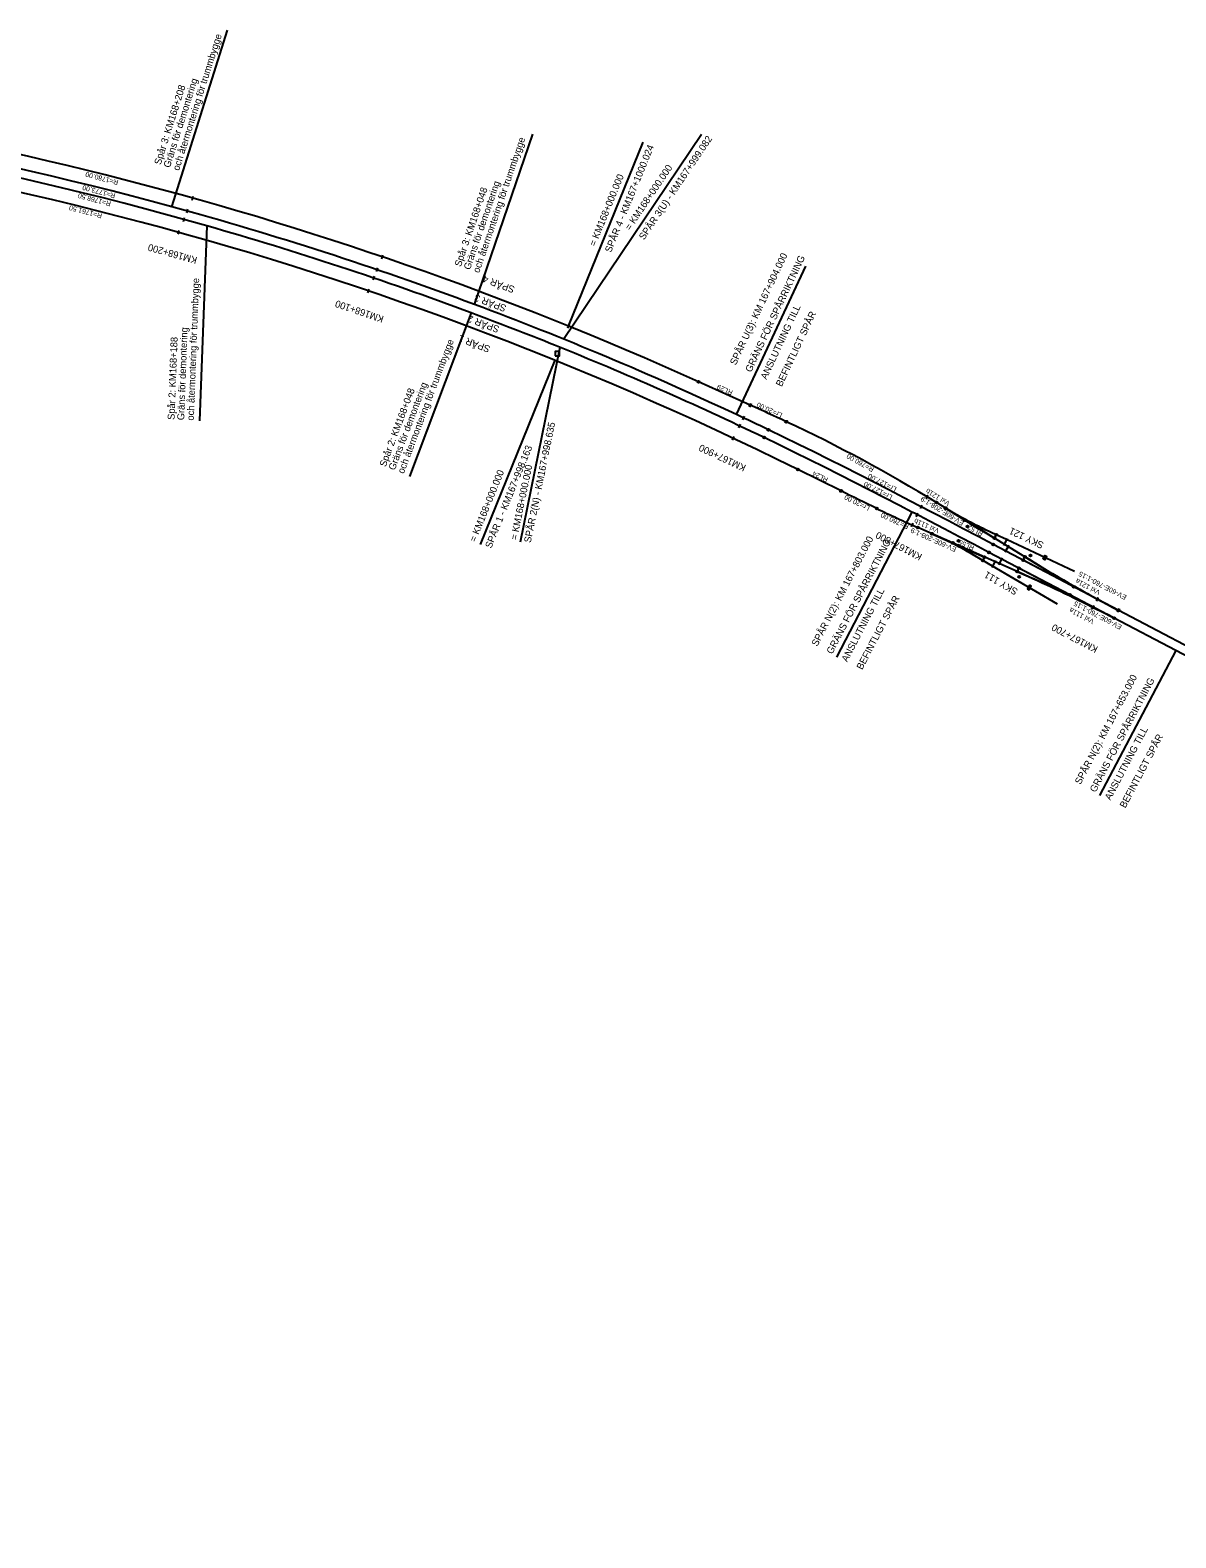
# Model space of a CAD drawing. Extents: x 185262 to 188870, y 6548921 to 6550022.
# Drawn here: x 186997 to 187573, y 6549174 to 6549933 of the extents above; entities that cross this region are included whole.
import ezdxf

# ---------------------------------------------------------------- set-up
doc = ezdxf.new("R2010")
doc.units = 0
for name, color, linetype in [('Befintligt spår som justeras', 7, 'Continuous'), ('BKS 1 verklig mangan P', 7, 'Continuous'), ('BKS 2 verklig mangan P', 7, 'Continuous'), ('FSK P', 7, 'Continuous'), ('Gräns för anslutning L', 7, 'Continuous'), ('Gräns för anslutning T', 7, 'Continuous'), ('Gräns för trummor L', 7, 'Continuous'), ('Gräns för trummor T', 7, 'Continuous'), ('Hinderpåle P', 7, 'Continuous'), ('Kilometertavla P', 7, 'Continuous'), ('Konnektion längdmätning L', 7, 'Continuous'), ('Konnektion längdmätning T', 7, 'Continuous'), ('Längdm markering (primär) L', 7, 'Continuous'), ('Längdmätning T', 7, 'Continuous'), ('MKP fiktiv P', 7, 'Continuous'), ('Spår bef projekterat behålls L', 7, 'Continuous'), ('Spår nr T', 7, 'Continuous'), ('Spår som demonteras och återmonteras', 7, 'Continuous'), ('Spårgeometri T', 7, 'Continuous'), ('Spårmitt projekterad L', 7, 'Continuous'), ('Spårmitt tp P', 7, 'Continuous'), ('Stoppbock P', 7, 'Continuous'), ('Växel linjevikt 2 L', 7, 'Continuous'), ('Växelnummer T', 7, 'Continuous'), ('Växeltyp T', 7, 'Continuous')]:
    doc.layers.add(name, color=color, linetype=linetype)

msp = doc.modelspace()

# ---------------------------------------------------------------- linework, layer by layer
at = {"layer": 'Befintligt spår som justeras'}
for p, q in [((187719.61, 6549548.75), (187481.29, 6549674.04)), ((187573.24, 6549620.62), (187479.19, 6549670.06))]:
    msp.add_line(p, q, dxfattribs=at)
for points in [[(187481.29, 6549674.04), (187473.8, 6549677.98), (187466.3, 6549681.92), (187458.8, 6549685.85), (187451.3, 6549689.78), (187443.8, 6549693.69), (187436.28, 6549697.59), (187428.76, 6549701.48), (187421.23, 6549705.36), (187413.69, 6549709.21), (187406.14, 6549713.04), (187398.58, 6549716.85), (187391.01, 6549720.63), (187383.42, 6549724.38), (187375.81, 6549728.1), (187368.19, 6549731.79)], [(187479.19, 6549670.06), (187471.7, 6549674), (187464.2, 6549677.94), (187456.7, 6549681.87), (187449.2, 6549685.8), (187441.7, 6549689.71), (187440.46, 6549690.35)]]:
    msp.add_lwpolyline(points, dxfattribs=at)
msp.add_arc((186599.87, 6548133.91), 1773, 64.32006, 64.89363, dxfattribs=at)
at = {"layer": 'BKS 1 verklig mangan P'}
for centre in [(187481.99, 6549677.2), (187476.99, 6549667.69), (187496.38, 6549666.11), (187494.28, 6549662.13)]:
    msp.add_circle(centre, 0.5, dxfattribs=at)
at = {"layer": 'BKS 2 verklig mangan P'}
for centre in [(187482.91, 6549678.9), (187476.11, 6549665.97), (187497.33, 6549667.78), (187493.45, 6549660.39)]:
    msp.add_circle(centre, 0.5, dxfattribs=at)
at = {"layer": 'FSK P'}
for centre in [(187457.26, 6549692.38), (187450.46, 6549679.46), (187542.27, 6549636.9), (187544.37, 6549640.88)]:
    msp.add_circle(centre, 0.5, dxfattribs=at)
at = {"layer": 'Gräns för anslutning L'}
for p, q in [((187352.15, 6549739.4), (187387.13, 6549814.04)), ((187440.46, 6549690.35), (187402.42, 6549617.23)), ((187573.24, 6549620.62), (187534.89, 6549547.66))]:
    msp.add_line(p, q, dxfattribs=at)
at = {"layer": 'Gräns för trummor L'}
for p, q in [((187068.08, 6549843.97), (187096.09, 6549932.91)), ((187220.28, 6549794.82), (187249.63, 6549880.48)), ((187085.63, 6549834.39), (187081.91, 6549736.23)), ((187218.59, 6549790.65), (187187.52, 6549708.32))]:
    msp.add_line(p, q, dxfattribs=at)
at = {"layer": 'Hinderpåle P'}
for centre, radius in [((187468.41, 6549683.13), 0.5), ((187468.41, 6549683.13), 0.2), ((187463.81, 6549675.8), 0.5), ((187463.81, 6549675.8), 0.2), ((187500.14, 6549668.49), 0.5), ((187500.14, 6549668.49), 0.2), ((187494.46, 6549657.68), 0.5), ((187494.46, 6549657.68), 0.2)]:
    msp.add_circle(centre, radius, dxfattribs=at)
at = {"layer": 'Kilometertavla P'}
msp.add_lwpolyline([(187260.9, 6549768.91), (187263.15, 6549768.91), (187263.15, 6549771.16), (187260.9, 6549771.16)], close=True, dxfattribs=at)
at = {"layer": 'Konnektion längdmätning L'}
for points in [[(187265.02, 6549777.42), (187334.47, 6549880.58)], [(187267.64, 6549783.91), (187305.16, 6549876.6)], [(187263.33, 6549773.25), (187243.33, 6549675.26)], [(187260.7, 6549766.76), (187223.18, 6549674.06)]]:
    msp.add_lwpolyline(points, dxfattribs=at)
at = {"layer": 'Längdm markering (primär) L'}
for points in [[(187078.16, 6549847.41), (187078.7, 6549849.34)], [(187075.52, 6549840.88), (187076.06, 6549842.81)], [(187073.82, 6549836.68), (187074.36, 6549838.61)], [(187071.18, 6549830.15), (187071.72, 6549832.08)], [(187173.62, 6549817.85), (187174.26, 6549819.74)], [(187170.99, 6549811.35), (187171.63, 6549813.25)], [(187169.3, 6549807.17), (187169.94, 6549809.07)], [(187166.67, 6549800.68), (187167.31, 6549802.57)], [(187267.29, 6549782.97), (187268.04, 6549784.82)], [(187358.94, 6549743.1), (187359.77, 6549744.92)], [(187353.25, 6549732.81), (187354.1, 6549734.62)], [(187355.35, 6549736.8), (187356.2, 6549738.6)], [(187350.19, 6549726.51), (187351.05, 6549728.32)], [(187447.55, 6549697.15), (187448.58, 6549698.86)], [(187442.64, 6549688.09), (187443.57, 6549689.86)], [(187444.74, 6549692.07), (187445.66, 6549693.85)], [(187440.21, 6549682.92), (187441.03, 6549684.74)], [(187533.27, 6549645.58), (187534.2, 6549647.36)], [(187533.32, 6549645.67), (187534.28, 6549647.42)], [(187531.16, 6549641.5), (187532.07, 6549643.29)], [(187531.18, 6549641.6), (187532.11, 6549643.37)], [(187543.9, 6549640), (187544.83, 6549641.77)]]:
    msp.add_lwpolyline(points, dxfattribs=at)
at = {"layer": 'MKP fiktiv P'}
for centre in [(187467.1, 6549686.34), (187461.02, 6549674.78), (187521.97, 6549652.66), (187519.88, 6549648.67)]:
    msp.add_circle(centre, 0.5, dxfattribs=at)
at = {"layer": 'Spår bef projekterat behålls L'}
msp.add_line((188422.73, 6549174.02), (187573.24, 6549620.62), dxfattribs=at)
msp.add_lwpolyline([(187440.46, 6549690.35), (187434.18, 6549693.61), (187426.66, 6549697.5), (187419.13, 6549701.38), (187411.59, 6549705.23), (187404.04, 6549709.06), (187396.48, 6549712.87), (187388.9, 6549716.65), (187381.31, 6549720.4), (187373.71, 6549724.12), (187366.09, 6549727.81)], dxfattribs=at)
for centre, radius, start, end in [((186599.87, 6548133.91), 1773, 74.68797, 85.4491), ((186599.86, 6548133.91), 1768.5, 74.0572, 85.26658), ((186599.86, 6548133.91), 1768.5, 68.06329, 69.52123), ((186599.87, 6548133.91), 1773, 64.89363, 69.51751), ((186599.86, 6548133.91), 1768.5, 64.32529, 68.06329)]:
    msp.add_arc(centre, radius, start, end, dxfattribs=at)
at = {"layer": 'Spår som demonteras och återmonteras'}
for centre, radius, start, end in [((186599.87, 6548133.91), 1773, 69.51751, 74.68797), ((186599.86, 6548133.91), 1768.5, 69.52123, 74.0572)]:
    msp.add_arc(centre, radius, start, end, dxfattribs=at)
at = {"layer": 'Spårmitt projekterad L'}
for p, q in [((187359.04, 6549744.15), (187333.01, 6549755.92)), ((187404.76, 6549700.95), (187382.96, 6549711.78)), ((187497.33, 6549667.78), (187452.74, 6549695.16)), ((187493.45, 6549660.39), (187443.47, 6549682.56)), ((187482.91, 6549678.9), (187477.54, 6549681.43)), ((187488.06, 6549676.47), (187482.91, 6549678.9)), ((187522.29, 6549660.36), (187488.06, 6549676.47)), ((187476.11, 6549665.97), (187470.99, 6549668.96)), ((187500.4, 6549665.9), (187497.33, 6549667.78)), ((187481.03, 6549663.1), (187476.11, 6549665.97)), ((187513.71, 6549644.04), (187481.03, 6549663.1)), ((187496.74, 6549658.93), (187493.45, 6549660.39))]:
    msp.add_line(p, q, dxfattribs=at)
for points in [[(187377.23, 6549735.84), (187374.96, 6549736.89), (187372.69, 6549737.94), (187370.42, 6549738.98), (187368.15, 6549740.02), (187365.87, 6549741.06), (187363.6, 6549742.09), (187361.32, 6549743.12), (187359.04, 6549744.15)], [(187422.72, 6549692.14), (187420.46, 6549693.23), (187418.21, 6549694.32), (187415.97, 6549695.42), (187413.72, 6549696.52), (187411.48, 6549697.62), (187409.24, 6549698.73), (187407, 6549699.84), (187404.76, 6549700.95)]]:
    msp.add_lwpolyline(points, dxfattribs=at)
for centre, radius, start, end in [((186599.87, 6548133.91), 1780, 65.67718, 86.05706), ((186599.86, 6548133.91), 1761.5, 63.60482, 87.36623), ((187055.12, 6549047.47), 760, 58.45394, 64.92329), ((187751.59, 6550377.3), 760, 244.35871, 246.08209), ((187566.31, 6549870.02), 208.44, 238.45394, 244.79413), ((187365.96, 6549488.92), 208.44, 59.7419, 66.08209), ((187188.62, 6548964.2), 760, 62.26802, 66.08209), ((187898.02, 6550313.58), 760, 238.45394, 242.26802)]:
    msp.add_arc(centre, radius, start, end, dxfattribs=at)
at = {"layer": 'Spårmitt tp P'}
for centre in [(187333.01, 6549755.92), (187359.04, 6549744.15), (187377.23, 6549735.84), (187366.09, 6549727.81), (187368.19, 6549731.79), (187382.96, 6549711.78), (187404.76, 6549700.95), (187422.72, 6549692.14), (187452.74, 6549695.16), (187443.47, 6549682.56), (187481.29, 6549674.04), (187479.19, 6549670.06)]:
    msp.add_circle(centre, 0.5, dxfattribs=at)
at = {"layer": 'Stoppbock P'}
for points in [[(187506.48, 6549666.7), (187507.33, 6549668.51), (187508.24, 6549668.08), (187507.39, 6549666.27)], [(187499.53, 6549653.47), (187498.52, 6549651.74), (187499.38, 6549651.24), (187500.39, 6549652.97)]]:
    msp.add_lwpolyline(points, close=True, dxfattribs=at)
at = {"layer": 'Växel linjevikt 2 L'}
for points in [[(187457.26, 6549692.38), (187467.1, 6549686.34)], [(187450.46, 6549679.46), (187461.02, 6549674.78)], [(187488.41, 6549677.11), (187486.5, 6549673.58)], [(187485.83, 6549667.38), (187484.08, 6549663.76)], [(187489.25, 6549673.59), (187487.26, 6549670.09)], [(187489.25, 6549673.59), (187487.26, 6549670.09)], [(187482.53, 6549666.03), (187480.7, 6549662.45)], [(187544.37, 6549640.88), (187521.97, 6549652.66)], [(187542.27, 6549636.9), (187519.88, 6549648.67)]]:
    msp.add_lwpolyline(points, dxfattribs=at)
for points in [[(187457.26, 6549692.38), (187481.99, 6549677.2), (187482.91, 6549678.9), (187477.54, 6549681.43), (187477.54, 6549681.43), (187476.32, 6549682.01), (187475.09, 6549682.6), (187473.88, 6549683.2), (187472.66, 6549683.8), (187471.45, 6549684.42), (187470.25, 6549685.04), (187469.04, 6549685.67), (187467.85, 6549686.3), (187466.65, 6549686.95), (187465.46, 6549687.6), (187464.28, 6549688.26), (187463.1, 6549688.93), (187461.92, 6549689.6), (187460.75, 6549690.29), (187459.58, 6549690.98), (187458.42, 6549691.68)], [(187467.1, 6549686.34), (187481.99, 6549677.2), (187482.91, 6549678.9)], [(187450.46, 6549679.46), (187476.99, 6549667.69), (187476.11, 6549665.97), (187470.99, 6549668.96), (187470.99, 6549668.96), (187469.81, 6549669.64), (187468.64, 6549670.31), (187467.45, 6549670.98), (187466.27, 6549671.63), (187465.07, 6549672.28), (187463.88, 6549672.92), (187462.68, 6549673.56), (187461.47, 6549674.18), (187460.27, 6549674.8), (187459.06, 6549675.41), (187457.84, 6549676.01), (187456.62, 6549676.61), (187455.4, 6549677.19), (187454.17, 6549677.77), (187452.94, 6549678.34), (187451.7, 6549678.9)], [(187461.02, 6549674.78), (187476.99, 6549667.69), (187476.11, 6549665.97)], [(187521.97, 6549652.66), (187496.38, 6549666.11), (187497.33, 6549667.78)], [(187544.37, 6549640.88), (187496.38, 6549666.11), (187497.33, 6549667.78), (187500.4, 6549665.9), (187500.4, 6549665.9), (187502.56, 6549664.58), (187504.72, 6549663.26), (187506.89, 6549661.96), (187509.06, 6549660.66), (187511.24, 6549659.37), (187513.42, 6549658.08), (187515.6, 6549656.81), (187517.79, 6549655.54), (187519.98, 6549654.28), (187522.18, 6549653.02), (187524.38, 6549651.78), (187526.58, 6549650.54), (187528.79, 6549649.3), (187531.01, 6549648.08), (187533.22, 6549646.86), (187535.44, 6549645.65), (187537.67, 6549644.45), (187539.9, 6549643.25), (187542.13, 6549642.06)], [(187519.88, 6549648.67), (187494.28, 6549662.13), (187493.45, 6549660.39)], [(187542.27, 6549636.9), (187494.28, 6549662.13), (187493.45, 6549660.39), (187496.74, 6549658.93), (187496.74, 6549658.93), (187499.05, 6549657.9), (187501.36, 6549656.87), (187503.66, 6549655.82), (187505.97, 6549654.77), (187508.26, 6549653.71), (187510.56, 6549652.64), (187512.84, 6549651.57), (187515.13, 6549650.48), (187517.41, 6549649.39), (187519.69, 6549648.29), (187521.97, 6549647.19), (187524.24, 6549646.08), (187526.51, 6549644.95), (187528.77, 6549643.83), (187531.03, 6549642.69), (187533.29, 6549641.55), (187535.54, 6549640.4), (187537.79, 6549639.24), (187540.03, 6549638.07)]]:
    msp.add_lwpolyline(points, close=True, dxfattribs=at)

# ---------------------------------------------------------------- texts
at = {"layer": 'Gräns för anslutning T'}
for s, rotation, p in [('SPÅR U(3): KM 167+904.000', 64.89363, (187351.82, 6549764)), ('GRÄNS FÖR SPÅRRIKTNING', 64.89363, (187359.52, 6549760.4)), ('ANSLUTNING TILL ', 64.89363, (187367.22, 6549756.79)), ('BEFINTLIGT SPÅR', 64.89363, (187374.91, 6549753.18)), ('SPÅR N(2): KM 167+803.000', 62.51186, (187392.79, 6549622.46)), ('GRÄNS FÖR SPÅRRIKTNING', 62.51186, (187400.33, 6549618.54)), ('ANSLUTNING TILL ', 62.51186, (187407.87, 6549614.61)), ('BEFINTLIGT SPÅR', 62.51186, (187415.41, 6549610.69)), ('SPÅR N(2): KM 167+653.000', 62.26802, (187525.28, 6549552.93)), ('GRÄNS FÖR SPÅRRIKTNING', 62.26802, (187532.81, 6549548.97)), ('ANSLUTNING TILL ', 62.26802, (187540.33, 6549545.02)), ('BEFINTLIGT SPÅR', 62.26802, (187547.85, 6549541.06))]:
    msp.add_text(s, height=3.5, rotation=rotation, dxfattribs=at).set_placement(p)
at = {"layer": 'Gräns för trummor T'}
for s, rotation, p in [('och återmontering för trummbygge', 72.51731, (187071.63, 6549861.93)), ('Spår 3: KM168+208', 72.51731, (187062.37, 6549864.85)), ('Gräns för demontering', 72.51731, (187067, 6549863.39)), ('och återmontering för trummbygge', 71.0895, (187222.64, 6549810.44)), ('Gräns för demontering', 71.0895, (187218.04, 6549812.01)), ('Spår 3: KM168+048', 71.0895, (187213.45, 6549813.58)), ('och återmontering för trummbygge', 87.82728, (187079.06, 6549736.34)), ('Gräns för demontering', 87.82728, (187074.2, 6549736.52)), ('Spår 2: KM168+188', 87.82728, (187069.35, 6549736.7)), ('och återmontering för trummbygge', 69.32366, (187184.7, 6549709.38)), ('Spår 2: KM168+048', 69.32366, (187175.62, 6549712.81)), ('Gräns för demontering', 69.32366, (187180.16, 6549711.09))]:
    msp.add_text(s, height=3.5, rotation=rotation, dxfattribs=at).set_placement(p)
at = {"layer": 'Konnektion längdmätning T'}
for s, rotation, p in [('SPÅR 3(U) - KM167+999.082 ', 56.05127, (187305.65, 6549827.03)), ('SPÅR 4 - KM167+1000.024', 67.9663, (187289, 6549820.68)), ('= KM168+000.000', 56.05127, (187298.6, 6549831.78)), ('= KM168+000.000', 67.9663, (187281.12, 6549823.86)), ('SPÅR 2(N) - KM167+998.635', 78.46668, (187248.59, 6549674.68)), ('SPÅR 1 - KM167+998.163', 67.96609, (187228.75, 6549671.81)), ('= KM168+000.000 ', 78.46668, (187241.73, 6549676.08)), ('= KM168+000.000', 67.96609, (187220.87, 6549675))]:
    msp.add_text(s, height=3.5, rotation=rotation, dxfattribs=at).set_placement(p)
at = {"layer": 'Längdmätning T'}
for s, rotation, p in [('KM168+200', 164.44568, (187081.02, 6549818.59)), ('KM168+100', 161.20589, (187174.95, 6549788.88)), ('KM167+900', 154.77052, (187357.23, 6549713.8)), ('KM167+800', 152.47975, (187445.87, 6549668.93)), ('KM167+700', 152.26802, (187534.37, 6549622.41))]:
    msp.add_text(s, height=3.5, rotation=rotation, dxfattribs=at).set_placement(p)
at = {"layer": 'Spår nr T'}
for s, rotation, p in [('SPÅR 4', 159.47472, (187240.89, 6549803.72)), ('SPÅR 3', 159.47472, (187236.64, 6549794.26)), ('SPÅR 2', 159.47472, (187233.15, 6549783.7)), ('SPÅR 1', 159.47472, (187228.54, 6549773.78)), ('SKY 121', 154.79413, (187507.16, 6549674.86)), ('SKY 111', 149.7419, (187494.1, 6549651.34))]:
    msp.add_text(s, height=3.5, rotation=rotation, dxfattribs=at).set_placement(p)
at = {"layer": 'Spårgeometri T'}
for s, rotation, p in [('R=1780.00', 165.40477, (187041.31, 6549857.35)), ('R=1768.50', 165.18933, (187037.57, 6549846.59)), ('R=1773.00', 165.15749, (187039.8, 6549850.65)), ('R=1761.50', 165.27049, (187033.11, 6549840.53)), ('RL29', 155.67718, (187350.52, 6549751.3)), ('Lr=20.00', 155.48871, (187375.48, 6549739.98)), ('R=760.00', 151.11946, (187421.63, 6549712.57)), ('RL24', 153.60482, (187398.48, 6549707.42)), ('Lr=127.00', 152.78233, (187430.9, 6549698.7)), ('Lr=127.00', 152.78103, (187433, 6549702.68)), ('Lr=20.00', 153.79329, (187419.51, 6549693.11)), ('R=760.00', 155.2204, (187439.14, 6549683.91)), ('RL52', 149.9119, (187476.5, 6549680.1)), ('RL55', 156.08209, (187472.04, 6549673.19))]:
    msp.add_text(s, height=2.5, rotation=rotation, dxfattribs=at).set_placement(p)
at = {"layer": 'Växelnummer T'}
for s, rotation, p in [('Vxl 121b', 148.45394, (187459.83, 6549695.35)), ('Vxl 111b', 156.08209, (187454.49, 6549681.8)), ('Vxl 121a', 152.26802, (187535.44, 6549650.68)), ('Vxl 111a', 152.26802, (187532.34, 6549636.08))]:
    msp.add_text(s, height=2.5, rotation=rotation, dxfattribs=at).set_placement(p)
at = {"layer": 'Växeltyp T'}
for s, rotation, p in [('EV-60E-208-1:9', 148.45394, (187466.88, 6549685.41)), ('EV-60E-208-1:9', 156.08209, (187463.08, 6549672.44)), ('EV-60E-760-1:15', 152.26802, (187548.76, 6549648.2)), ('EV-60E-760-1:15', 152.26802, (187546.33, 6549633.25))]:
    msp.add_text(s, height=2.5, rotation=rotation, dxfattribs=at).set_placement(p)

doc.saveas('drawing.dxf')
